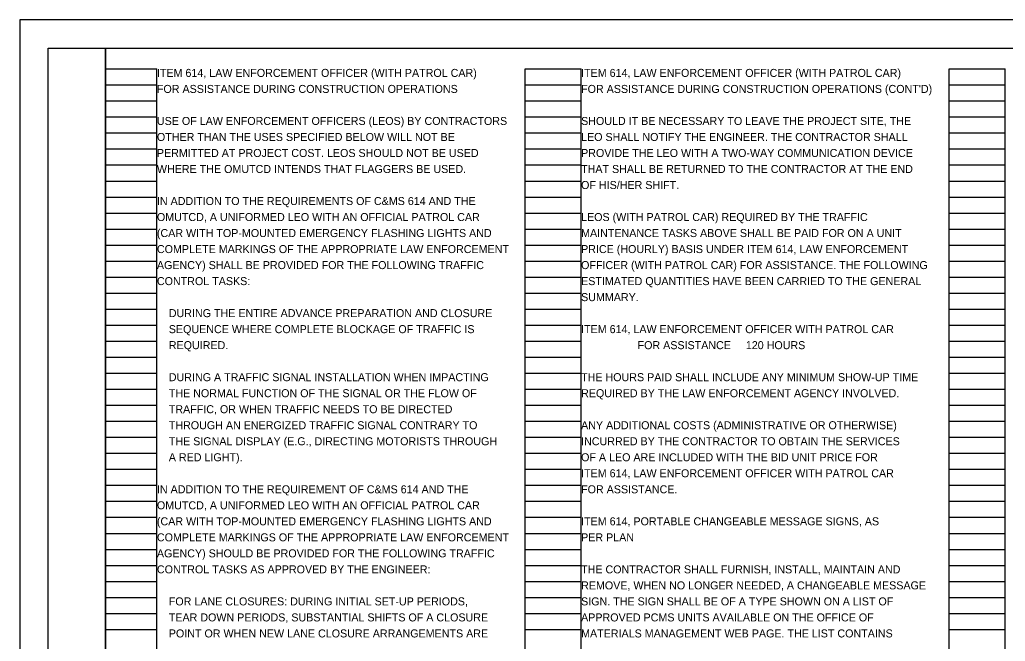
# Model space of a CAD drawing. Extents: x 0 to 34, y 0 to 22.
# Drawn here: x 0 to 17.24, y 11.13 to 22 of the extents above; entities that cross this region are included whole.
import ezdxf

# ---------------------------------------------------------------- set-up
doc = ezdxf.new("R2010")
doc.units = 0
for name, color, linetype in [('SC_Scratch1', 7, 'Continuous'), ('SH_Border', 7, 'Continuous'), ('SH_Cut_Line', 7, 'Continuous'), ('SH_Text', 7, 'Continuous')]:
    doc.layers.add(name, color=color, linetype=linetype)

msp = doc.modelspace()

# ---------------------------------------------------------------- linework, layer by layer
at = {"layer": 'SC_Scratch1'}
for p, q in [((1.5, 0.98), (1.5, 21.14)), ((1.5, 21.14), (2.4, 21.14)), ((2.4, 0.98), (2.4, 21.14)), ((8.84, 0.98), (8.84, 21.14)), ((8.84, 21.14), (9.82, 21.14)), ((9.82, 0.98), (9.82, 21.14)), ((16.26, 0.98), (16.26, 21.14)), ((16.26, 21.14), (17.24, 21.14)), ((17.24, 0.98), (17.24, 21.14)), ((1.5, 20.86), (2.4, 20.86)), ((8.84, 20.86), (9.82, 20.86)), ((16.26, 20.86), (17.24, 20.86)), ((1.5, 20.58), (2.4, 20.58)), ((8.84, 20.58), (9.82, 20.58)), ((16.26, 20.58), (17.24, 20.58)), ((1.5, 20.3), (2.4, 20.3)), ((8.84, 20.3), (9.82, 20.3)), ((16.26, 20.3), (17.24, 20.3)), ((1.5, 20.02), (2.4, 20.02)), ((8.84, 20.02), (9.82, 20.02)), ((16.26, 20.02), (17.24, 20.02)), ((1.5, 19.74), (2.4, 19.74)), ((8.84, 19.74), (9.82, 19.74)), ((16.26, 19.74), (17.24, 19.74)), ((1.5, 19.46), (2.4, 19.46)), ((8.84, 19.46), (9.82, 19.46)), ((16.26, 19.46), (17.24, 19.46)), ((1.5, 19.18), (2.4, 19.18)), ((8.84, 19.18), (9.82, 19.18)), ((16.26, 19.18), (17.24, 19.18)), ((1.5, 18.9), (2.4, 18.9)), ((8.84, 18.9), (9.82, 18.9)), ((16.26, 18.9), (17.24, 18.9)), ((1.5, 18.62), (2.4, 18.62)), ((8.84, 18.62), (9.82, 18.62)), ((16.26, 18.62), (17.24, 18.62)), ((1.5, 18.34), (2.4, 18.34)), ((8.84, 18.34), (9.82, 18.34)), ((16.26, 18.34), (17.24, 18.34)), ((1.5, 18.06), (2.4, 18.06)), ((8.84, 18.06), (9.82, 18.06)), ((16.26, 18.06), (17.24, 18.06)), ((1.5, 17.78), (2.4, 17.78)), ((8.84, 17.78), (9.82, 17.78)), ((16.26, 17.78), (17.24, 17.78)), ((1.5, 17.5), (2.4, 17.5)), ((8.84, 17.5), (9.82, 17.5)), ((16.26, 17.5), (17.24, 17.5)), ((1.5, 17.22), (2.4, 17.22)), ((8.84, 17.22), (9.82, 17.22)), ((16.26, 17.22), (17.24, 17.22)), ((1.5, 16.94), (2.4, 16.94)), ((8.84, 16.94), (9.82, 16.94)), ((16.26, 16.94), (17.24, 16.94)), ((1.5, 16.66), (2.4, 16.66)), ((8.84, 16.66), (9.82, 16.66)), ((16.26, 16.66), (17.24, 16.66)), ((1.5, 16.38), (2.4, 16.38)), ((8.84, 16.38), (9.82, 16.38)), ((16.26, 16.38), (17.24, 16.38)), ((1.5, 16.1), (2.4, 16.1)), ((8.84, 16.1), (9.82, 16.1)), ((16.26, 16.1), (17.24, 16.1)), ((1.5, 15.82), (2.4, 15.82)), ((8.84, 15.82), (9.82, 15.82)), ((16.26, 15.82), (17.24, 15.82)), ((1.5, 15.54), (2.4, 15.54)), ((8.84, 15.54), (9.82, 15.54)), ((16.26, 15.54), (17.24, 15.54)), ((1.5, 15.26), (2.4, 15.26)), ((8.84, 15.26), (9.82, 15.26)), ((16.26, 15.26), (17.24, 15.26)), ((1.5, 14.98), (2.4, 14.98)), ((8.84, 14.98), (9.82, 14.98)), ((16.26, 14.98), (17.24, 14.98)), ((1.5, 14.7), (2.4, 14.7)), ((8.84, 14.7), (9.82, 14.7)), ((16.26, 14.7), (17.24, 14.7)), ((1.5, 14.42), (2.4, 14.42)), ((8.84, 14.42), (9.82, 14.42)), ((16.26, 14.42), (17.24, 14.42)), ((1.5, 14.14), (2.4, 14.14)), ((8.84, 14.14), (9.82, 14.14)), ((16.26, 14.14), (17.24, 14.14)), ((1.5, 13.86), (2.4, 13.86)), ((8.84, 13.86), (9.82, 13.86)), ((16.26, 13.86), (17.24, 13.86)), ((1.5, 13.58), (2.4, 13.58)), ((8.84, 13.58), (9.82, 13.58)), ((16.26, 13.58), (17.24, 13.58)), ((1.5, 13.3), (2.4, 13.3)), ((8.84, 13.3), (9.82, 13.3)), ((16.26, 13.3), (17.24, 13.3)), ((1.5, 13.02), (2.4, 13.02)), ((8.84, 13.02), (9.82, 13.02)), ((16.26, 13.02), (17.24, 13.02)), ((1.5, 12.74), (2.4, 12.74)), ((8.84, 12.74), (9.82, 12.74)), ((16.26, 12.74), (17.24, 12.74)), ((1.5, 12.46), (2.4, 12.46)), ((8.84, 12.46), (9.82, 12.46)), ((16.26, 12.46), (17.24, 12.46)), ((1.5, 12.18), (2.4, 12.18)), ((8.84, 12.18), (9.82, 12.18)), ((16.26, 12.18), (17.24, 12.18)), ((1.5, 11.9), (2.4, 11.9)), ((8.84, 11.9), (9.82, 11.9)), ((16.26, 11.9), (17.24, 11.9)), ((1.5, 11.62), (2.4, 11.62)), ((8.84, 11.62), (9.82, 11.62)), ((16.26, 11.62), (17.24, 11.62)), ((1.5, 11.34), (2.4, 11.34)), ((8.84, 11.34), (9.82, 11.34)), ((16.26, 11.34), (17.24, 11.34))]:
    msp.add_line(p, q, dxfattribs=at)
at = {"layer": 'SH_Border'}
for points in [[(0.5, 21.5), (1.5, 21.5), (1.5, 0.5), (0.5, 0.5)], [(1.5, 21.5), (33.5, 21.5), (33.5, 0.5), (1.5, 0.5)]]:
    msp.add_lwpolyline(points, close=True, dxfattribs=at)
at = {"layer": 'SH_Cut_Line'}
msp.add_lwpolyline([(0, 0), (34, 0), (34, 22), (0, 22)], close=True, dxfattribs=at)

# ---------------------------------------------------------------- texts
at = {"layer": 'SH_Text'}
for s, p in [('ITEM 614, LAW ENFORCEMENT OFFICER (WITH PATROL CAR)', (2.4, 21)), ('ITEM 614, LAW ENFORCEMENT OFFICER (WITH PATROL CAR)', (9.82, 21)), ('FOR ASSISTANCE DURING CONSTRUCTION OPERATIONS', (2.4, 20.72)), ("FOR ASSISTANCE DURING CONSTRUCTION OPERATIONS (CONT'D)", (9.82, 20.72)), ('USE OF LAW ENFORCEMENT OFFICERS (LEOS) BY CONTRACTORS', (2.4, 20.16)), ('SHOULD IT BE NECESSARY TO LEAVE THE PROJECT SITE, THE', (9.82, 20.16)), ('OTHER THAN THE USES SPECIFIED BELOW WILL NOT BE', (2.4, 19.88)), ('LEO SHALL NOTIFY THE ENGINEER. THE CONTRACTOR SHALL', (9.82, 19.88)), ('PERMITTED AT PROJECT COST. LEOS SHOULD NOT BE USED', (2.4, 19.6)), ('PROVIDE THE LEO WITH A TWO-WAY COMMUNICATION DEVICE', (9.82, 19.6)), ('WHERE THE OMUTCD INTENDS THAT FLAGGERS BE USED.', (2.4, 19.32)), ('THAT SHALL BE RETURNED TO THE CONTRACTOR AT THE END', (9.82, 19.32)), ('OF HIS/HER SHIFT.', (9.82, 19.04)), ('IN ADDITION TO THE REQUIREMENTS OF C&MS 614 AND THE', (2.4, 18.76)), ('OMUTCD, A UNIFORMED LEO WITH AN OFFICIAL PATROL CAR', (2.4, 18.48)), ('LEOS (WITH PATROL CAR) REQUIRED BY THE TRAFFIC', (9.82, 18.48)), ('(CAR WITH TOP-MOUNTED EMERGENCY FLASHING LIGHTS AND', (2.4, 18.2)), ('MAINTENANCE TASKS ABOVE SHALL BE PAID FOR ON A UNIT', (9.82, 18.2)), ('COMPLETE MARKINGS OF THE APPROPRIATE LAW ENFORCEMENT', (2.4, 17.92)), ('PRICE (HOURLY) BASIS UNDER ITEM 614, LAW ENFORCEMENT', (9.82, 17.92)), ('AGENCY) SHALL BE PROVIDED FOR THE FOLLOWING TRAFFIC', (2.4, 17.64)), ('OFFICER (WITH PATROL CAR) FOR ASSISTANCE. THE FOLLOWING', (9.82, 17.64)), ('CONTROL TASKS:', (2.4, 17.36)), ('ESTIMATED QUANTITIES HAVE BEEN CARRIED TO THE GENERAL', (9.82, 17.36)), ('SUMMARY.', (9.82, 17.08)), ('    DURING THE ENTIRE ADVANCE PREPARATION AND CLOSURE', (2.4, 16.8)), ('    SEQUENCE WHERE COMPLETE BLOCKAGE OF TRAFFIC IS', (2.4, 16.52)), ('ITEM 614, LAW ENFORCEMENT OFFICER WITH PATROL CAR', (9.82, 16.52)), ('    REQUIRED.', (2.4, 16.24)), ('                   FOR ASSISTANCE     120 HOURS', (9.82, 16.24)), ('    DURING A TRAFFIC SIGNAL INSTALLATION WHEN IMPACTING', (2.4, 15.68)), ('THE HOURS PAID SHALL INCLUDE ANY MINIMUM SHOW-UP TIME', (9.82, 15.68)), ('    THE NORMAL FUNCTION OF THE SIGNAL OR THE FLOW OF', (2.4, 15.4)), ('REQUIRED BY THE LAW ENFORCEMENT AGENCY INVOLVED.', (9.82, 15.4)), ('    TRAFFIC, OR WHEN TRAFFIC NEEDS TO BE DIRECTED', (2.4, 15.12)), ('    THROUGH AN ENERGIZED TRAFFIC SIGNAL CONTRARY TO', (2.4, 14.84)), ('ANY ADDITIONAL COSTS (ADMINISTRATIVE OR OTHERWISE)', (9.82, 14.84)), ('    THE SIGNAL DISPLAY (E.G., DIRECTING MOTORISTS THROUGH', (2.4, 14.56)), ('INCURRED BY THE CONTRACTOR TO OBTAIN THE SERVICES', (9.82, 14.56)), ('    A RED LIGHT).', (2.4, 14.28)), ('OF A LEO ARE INCLUDED WITH THE BID UNIT PRICE FOR', (9.82, 14.28)), ('ITEM 614, LAW ENFORCEMENT OFFICER WITH PATROL CAR', (9.82, 14)), ('IN ADDITION TO THE REQUIREMENT OF C&MS 614 AND THE', (2.4, 13.72)), ('FOR ASSISTANCE.', (9.82, 13.72)), ('OMUTCD, A UNIFORMED LEO WITH AN OFFICIAL PATROL CAR', (2.4, 13.44)), ('(CAR WITH TOP-MOUNTED EMERGENCY FLASHING LIGHTS AND', (2.4, 13.16)), ('ITEM 614, PORTABLE CHANGEABLE MESSAGE SIGNS, AS', (9.82, 13.16)), ('COMPLETE MARKINGS OF THE APPROPRIATE LAW ENFORCEMENT', (2.4, 12.88)), ('PER PLAN', (9.82, 12.88)), ('AGENCY) SHOULD BE PROVIDED FOR THE FOLLOWING TRAFFIC', (2.4, 12.6)), ('CONTROL TASKS AS APPROVED BY THE ENGINEER:', (2.4, 12.32)), ('THE CONTRACTOR SHALL FURNISH, INSTALL, MAINTAIN AND', (9.82, 12.32)), ('REMOVE, WHEN NO LONGER NEEDED, A CHANGEABLE MESSAGE', (9.82, 12.04)), ('    FOR LANE CLOSURES: DURING INITIAL SET-UP PERIODS,', (2.4, 11.76)), ('SIGN. THE SIGN SHALL BE OF A TYPE SHOWN ON A LIST OF', (9.82, 11.76)), ('    TEAR DOWN PERIODS, SUBSTANTIAL SHIFTS OF A CLOSURE', (2.4, 11.48)), ('APPROVED PCMS UNITS AVAILABLE ON THE OFFICE OF', (9.82, 11.48)), ('    POINT OR WHEN NEW LANE CLOSURE ARRANGEMENTS ARE', (2.4, 11.2)), ('MATERIALS MANAGEMENT WEB PAGE. THE LIST CONTAINS', (9.82, 11.2))]:
    msp.add_text(s, height=0.14, dxfattribs=at).set_placement(p)

doc.saveas('drawing.dxf')
